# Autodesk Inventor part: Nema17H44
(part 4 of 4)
sketch "Эскиз150"
  geometry: L1 (-96.15, 213.848)-(-96.15, 216.33) reference; L2 (-103.85, 213.848)-(-96.15, 213.848) reference; L3 (-103.85, 216.33)-(-103.85, 213.848) reference; L4 (-92.5, 209.772)-(-107.5, 209.772) reference; L5 (-92.5, 204.772)-(-92.5, 209.772) reference; L6 (-107.5, 204.772)-(-92.5, 204.772) reference; L7 (-107.5, 209.772)-(-107.5, 204.772) reference; L8 (-107.5, 211.772)-(-107.5, 202.772); L9 (-107.5, 202.772)-(-92.5, 202.772); L10 (-92.5, 202.772)-(-92.5, 211.772); L11 (-103.85, 213.848)-(-103.85, 211.748); L12 (-103.85, 211.748)-(-96.15, 211.748); L13 (-96.15, 211.748)-(-96.15, 213.848); L14 (-92.5, 211.772)-(-96.15, 211.772); L15 (-103.85, 211.772)-(-107.5, 211.772); L16 (-100, 225.696)-(-100, 229.696); L17 (-112, 225.696)-(-112, 229.696); L18 (-88, 229.696)-(-88, 225.696); L19 (-96.15, 213.848)-(-98.096, 213.848); L20 (-101.904, 213.848)-(-103.85, 213.848); L21 (-84.45, 245.246)-(-84.45, 241.246); L22 (-85.85, 245.246)-(-85.85, 241.246); L23 (-83.05, 241.246)-(-83.05, 245.246); L24 (-84.45, 243.246)-(-115.55, 243.246); L25 (-115.55, 243.246)-(-115.55, 212.146); L26 (-115.55, 212.146)-(-84.45, 212.146); L27 (-84.45, 212.146)-(-84.45, 243.246); L28 (-84.45, 214.146)-(-84.45, 210.146); L29 (-85.85, 214.146)-(-85.85, 210.146); L30 (-83.05, 210.146)-(-83.05, 214.146); L31 (-115.55, 245.246)-(-115.55, 241.246); L32 (-116.95, 245.246)-(-116.95, 241.246); L33 (-114.15, 241.246)-(-114.15, 245.246); L34 (-115.55, 214.146)-(-115.55, 210.146); L35 (-116.95, 214.146)-(-116.95, 210.146); L36 (-114.15, 210.146)-(-114.15, 214.146); L37 (-124, 246.139)-(-124, -18.443) reference; L38 (-124, 113.848)-(-84.45, 113.848); L39 (-103.85, 13.848)-(-96.15, 13.848); L40 (-96.15, 13.848)-(-98.096, 13.848); L41 (-101.904, 13.848)-(-103.85, 13.848); L42 (-103.85, 15.924)-(-107.5, 15.924); L43 (-103.85, 13.848)-(-103.85, 15.948); L44 (-103.85, 15.948)-(-96.15, 15.948); L45 (-96.15, 15.948)-(-96.15, 13.848); L46 (-92.5, 15.924)-(-96.15, 15.924); L47 (-96.15, 13.848)-(-96.15, 11.366); L48 (-103.85, 11.366)-(-103.85, 13.848); L49 (-100, 2)-(-100, -2); L50 (-115.55, 15.55)-(-84.45, 15.55); L51 (-84.45, 15.55)-(-84.45, -15.55); L52 (-112, 2)-(-112, -2); L53 (-84.45, -15.55)-(-115.55, -15.55); L54 (-88, -2)-(-88, 2); L55 (-92.5, 17.924)-(-107.5, 17.924); L56 (-92.5, 22.924)-(-92.5, 17.924); L57 (-107.5, 22.924)-(-92.5, 22.924); L58 (-107.5, 17.924)-(-107.5, 22.924); L59 (-107.5, 15.924)-(-107.5, 24.924); L60 (-107.5, 24.924)-(-92.5, 24.924); L61 (-92.5, 24.924)-(-92.5, 15.924); L62 (-85.85, 13.55)-(-85.85, 17.55); L63 (-84.45, 13.55)-(-84.45, 17.55); L64 (-83.05, 17.55)-(-83.05, 13.55)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; C1 r 1.4 at (-84.45, 243.246) reference; C2 r 1.4 at (-84.45, 212.146) reference; C3 r 1.4 at (-115.55, 212.146) reference; C4 r 1.4 at (-115.55, 243.246) reference; C5 r 1.4 at (-84.45, 15.55); C6 r 1.4 at (-115.55, 15.55); C7 r 1.4 at (-115.55, -15.55); C8 r 1.4 at (-84.45, -15.55); A1 r 12 centre (-100, 227.696) between (-96.15, 216.33) and (-103.85, 216.33) reference; A2 r 12 centre (-100, 229.696) between (-88, 229.696) and (-112, 229.696); A3 r 12 centre (-100, 225.696) between (-112, 225.696) and (-101.904, 213.848); A4 r 12 centre (-100, 225.696) between (-98.096, 213.848) and (-88, 225.696); A5 r 1.4 centre (-84.45, 245.246) between (-83.05, 245.246) and (-85.85, 245.246); A6 r 1.4 centre (-84.45, 241.246) between (-85.85, 241.246) and (-83.05, 241.246); A7 r 1.4 centre (-84.45, 210.146) between (-85.85, 210.146) and (-83.05, 210.146); A8 r 1.4 centre (-84.45, 214.146) between (-83.05, 214.146) and (-85.85, 214.146); A9 r 1.4 centre (-115.55, 241.246) between (-116.95, 241.246) and (-114.15, 241.246); A10 r 1.4 centre (-115.55, 245.246) between (-114.15, 245.246) and (-116.95, 245.246); A11 r 1.4 centre (-115.55, 210.146) between (-116.95, 210.146) and (-114.15, 210.146); A12 r 1.4 centre (-115.55, 214.146) between (-114.15, 214.146) and (-116.95, 214.146); A13 r 12 centre (-100, 0) between (-103.85, 11.366) and (-96.15, 11.366); A14 r 12 centre (-100, 2) between (-101.904, 13.848) and (-112, 2); A15 r 12 centre (-100, 2) between (-88, 2) and (-98.096, 13.848); A16 r 12 centre (-100, -2) between (-112, -2) and (-88, -2); A17 r 1.4 centre (-84.45, 13.55) between (-85.85, 13.55) and (-83.05, 13.55); A18 r 1.4 centre (-84.45, 17.55) between (-83.05, 17.55) and (-85.85, 17.55); A19 r 1.4 centre (-115.55, 17.55) between (-114.15, 17.55) and (-116.95, 17.55); A20 r 1.4 centre (-115.55, 13.55) between (-116.95, 13.55) and (-114.15, 13.55); A21 r 1.4 centre (-115.55, -13.55) between (-114.15, -13.55) and (-116.95, -13.55); A22 r 1.4 centre (-115.55, -17.55) between (-116.95, -17.55) and (-114.15, -17.55); A23 r 1.4 centre (-84.45, -17.55) between (-85.85, -17.55) and (-83.05, -17.55); A24 r 1.4 centre (-84.45, -13.55) between (-83.05, -13.55) and (-85.85, -13.55); 15 further points
  constraints: 152 end point, 56 symmetric about line, 46 point on circle, 27 centre point, 10 parallel, 10 tangent, 7 horizontal, 5 collinear, 5 perpendicular, 4 point on line, 4 vertical, 3 midpoint, 49 other
  dimensions: "d990" = 2 distance between parallel lines of L6 L9; "d991" = 2.1 distance of L11.end L11.start; "d992" = 2 distance between parallel lines of L4 L14; "d993" = 2 distance of A1.centre L16.end; "d994" = 2 distance of L24.start L21.end; "d995" = 31.1 distance of L26.end L24.start (derived); "d998" = 31.1 distance of L21.end L28.end (derived); "d1001" = 31.1 distance of L21.end L31.end (derived)
extrude "Выдавливание121" cut sketch "Эскиз150" distance "d1004" = 4; taper "d1005" = 0 deg
fillet "Сопряжение51" dims "d1006" = 1
sketch "Эскиз151"
  geometry: C1 r 6.8 at (0, 0) reference; C2 r 6.8 at (0, -227.696) reference; 1 further point
extrude "Выдавливание122" join sketch "Эскиз151" stored distance "d1007" = 98; taper "d1008" = 0 deg
fillet "Сопряжение52" dims "d1009" = 5
fillet "Сопряжение53" dims "d1010" = 5
sketch "Эскиз152"
  geometry: L1 (-124, 16.443)-(-124, 20.443); L2 (-120.75, 16.443)-(-120.75, 20.443); L3 (-127.25, 20.443)-(-127.25, 16.443); L4 (-124, 248.139)-(-124, 244.139); L5 (-127.25, 248.139)-(-127.25, 244.139); L6 (-120.75, 244.139)-(-120.75, 248.139); C1 r 4.05 at (-124, 18.443) reference; C2 r 4.05 at (-124, 246.139) reference; C3 r 3.25 at (-124, 18.443); A1 r 3.25 centre (-124, 16.443) between (-127.25, 16.443) and (-120.75, 16.443); A2 r 3.25 centre (-124, 20.443) between (-120.75, 20.443) and (-127.25, 20.443); A3 r 3.25 centre (-124, 248.139) between (-120.75, 248.139) and (-127.25, 248.139); A4 r 3.25 centre (-124, 244.139) between (-127.25, 244.139) and (-120.75, 244.139); 1 further point
  constraints: 16 end point, 9 tangent, 8 point on circle, 5 centre point, 2 midpoint, 2 parallel, 2 vertical, 1 coincident, 1 collinear, 1 equal radius
  dimensions: "d1011" = 2 distance of C1.centre L1.end; "d1012" = 6.5 diameter of C3
extrude "Выдавливание123" cut sketch "Эскиз152" distance "d1013" = 10; taper "d1014" = 0 deg
node "РабПлоскость14"
sketch "Эскиз153" dims "d1020" = 12
  geometry: L1 (-18.21, -243.972)-(-18.21, -263.972); L2 (-18.21, -243.972)-(-20.91, -243.972); L3 (-20.91, -243.972)-(-19.63, -245.252); L4 (-19.63, -245.252)-(-19.63, -263.472); L5 (-19.63, -263.472)-(-19.13, -263.972); L6 (-19.13, -263.972)-(-18.21, -263.972); L7 (-35.46, -275.972)-(-0.96, -275.972) reference; 3 further points
  constraints: 12 end point, 3 horizontal, 2 parallel, 1 perpendicular, 1 point on line, 1 vertical, 1 vertical alignment, 2 other
  dimensions: "d1015" = 5.4 diameter of L2.end L1; "d1016" = 2.84 diameter of L4 L1; "d1017" = 20 distance of L1.end L1.start; "d1018" = 45 deg angle of L6 L5; "d1019" = 0.5 horizontal distance of L4.end L5.end
revolve "Вращение3" sketch "Эскиз153" stored, may be unused: angle "d1021" = 90 deg
sketch "Эскиз154"
  geometry: L1 (-25.71, -238.252)-(-10.71, -238.252); L2 (-10.71, -238.252)-(-10.71, -245.252); L3 (-10.71, -245.252)-(-25.71, -245.252); L4 (-25.71, -245.252)-(-25.71, -238.252); L5 (-20.91, -245.252)-(-15.51, -245.252); L6 (-15.51, -245.252)-(-15.51, -243.372); L7 (-15.51, -243.372)-(-20.91, -243.372); L8 (-20.91, -243.372)-(-20.91, -245.252); L9 (-19.63, -245.252)-(-16.79, -245.252) reference; L10 (-20.91, -243.972)-(-15.51, -243.972) reference; L11 (-20.91, -243.972)-(-19.63, -245.252) reference; L12 (-25.71, -245.252)-(-20.91, -245.252); L13 (-18.21, -238.252)-(-18.21, -245.252); 3 further points
  constraints: 20 end point, 4 parallel, 3 horizontal, 3 midpoint, 3 point on line, 2 perpendicular, 1 collinear, 1 vertical alignment
  dimensions: "d1022" = 7 distance of L1.end L2.end; "d1023" = 15 distance of L1.start L1.end; "d1024" = 0.6 distance between parallel lines of L10 L7
revolve "Вращение4" sketch "Эскиз154" stored, may be unused: angle "d1025" = 90 deg
chamfer "Фаска48" distance "d1026" = 1; stored, may be unused: second distance "d1027" = 2, angle "d1028" = 45 deg
sketch "Эскиз155"
  geometry: C1 r 6.5 at (0, 0) reference; A1 r 7.5 centre (0, 0) between (7.499, -0.146) and (6.791, -3.184) reference; A2 r 1 centre (7.499, -0.146) between (7.038, 0.741) and (7.004, -1.015); A3 r 0.627 centre (6.694, -1.56) between (6.731, -2.185) and (7.004, -1.015); A4 r 1 centre (6.791, -3.184) between (6.731, -2.185) and (5.985, -3.776); A5 r 7.077 centre (0, 0) between (7.004, -1.015) and (5.985, -3.776); A6 r 1 centre (7.499, -0.146) between (7.038, 0.741) and (7.004, -1.015); A7 r 0.627 centre (6.75, 1.298) between (7.038, 0.741) and (6.811, 1.921); A8 r 1 centre (6.91, 2.916) between (6.128, 3.54) and (6.811, 1.921); A9 r 1 centre (6.91, 2.916) between (6.128, 3.54) and (6.811, 1.921); A10 r 0.627 centre (5.639, 3.931) between (6.128, 3.54) and (5.441, 4.525); A11 r 1 centre (5.126, 5.475) between (4.159, 5.727) and (5.441, 4.525); A12 r 1 centre (5.126, 5.475) between (4.159, 5.727) and (5.441, 4.525); A13 r 0.627 centre (3.552, 5.884) between (4.159, 5.727) and (3.13, 6.347); A14 r 1 centre (2.456, 7.086) between (1.47, 6.923) and (3.13, 6.347); A15 r 1 centre (2.456, 7.086) between (1.47, 6.923) and (3.13, 6.347); A16 r 0.627 centre (0.852, 6.821) between (1.47, 6.923) and (0.278, 7.072); A17 r 1 centre (-0.638, 7.473) between (-1.473, 6.922) and (0.278, 7.072); A18 r 1 centre (-0.638, 7.473) between (-1.473, 6.922) and (0.278, 7.072); A19 r 0.627 centre (-1.996, 6.577) between (-1.473, 6.922) and (-2.623, 6.573); A20 r 1 centre (-3.623, 6.567) between (-4.161, 5.725) and (-2.623, 6.573); A21 r 1 centre (-3.623, 6.567) between (-4.161, 5.725) and (-2.623, 6.573); A22 r 0.627 centre (-4.499, 5.197) between (-4.161, 5.725) and (-5.069, 4.938); A23 r 1 centre (-5.98, 4.526) between (-6.13, 3.537) and (-5.069, 4.938); A24 r 1 centre (-5.98, 4.526) between (-6.13, 3.537) and (-5.069, 4.938); A25 r 0.627 centre (-6.223, 2.918) between (-6.13, 3.537) and (-6.64, 2.45); A26 r 1 centre (-7.304, 1.702) between (-7.039, 0.738) and (-6.64, 2.45); A27 r 1 centre (-7.304, 1.702) between (-7.039, 0.738) and (-6.64, 2.45); A28 r 0.627 centre (-6.872, 0.134) between (-7.039, 0.738) and (-7.062, -0.463); A29 r 1 centre (-7.365, -1.416) between (-6.73, -2.189) and (-7.062, -0.463); A30 r 1 centre (-7.365, -1.416) between (-6.73, -2.189) and (-7.062, -0.463); A31 r 0.627 centre (-6.333, -2.673) between (-6.73, -2.189) and (-6.263, -3.295); A32 r 1 centre (-6.153, -4.289) between (-5.258, -4.737) and (-6.263, -3.295); A33 r 1 centre (-6.153, -4.289) between (-5.258, -4.737) and (-6.263, -3.295); A34 r 0.627 centre (-4.698, -5.017) between (-5.258, -4.737) and (-4.381, -5.558); A35 r 1 centre (-3.876, -6.421) between (-2.877, -6.466) and (-4.381, -5.558); A36 r 1 centre (-3.876, -6.421) between (-2.877, -6.466) and (-4.381, -5.558); A37 r 0.627 centre (-2.251, -6.494) between (-2.877, -6.466) and (-1.742, -6.859); A38 r 1 centre (-0.929, -7.442) between (0.002, -7.077) and (-1.742, -6.859); A39 r 1 centre (-0.929, -7.442) between (0.002, -7.077) and (-1.742, -6.859); A40 r 0.627 centre (0.585, -6.849) between (0.002, -7.077) and (1.199, -6.975); A41 r 1 centre (2.178, -7.177) between (2.88, -6.465) and (1.199, -6.975); A42 r 1 centre (2.178, -7.177) between (2.88, -6.465) and (1.199, -6.975); A43 r 0.627 centre (3.32, -6.019) between (2.88, -6.465) and (3.932, -5.884); A44 r 1 centre (4.909, -5.67) between (5.26, -4.734) and (3.932, -5.884); A45 r 1 centre (4.909, -5.67) between (5.26, -4.734) and (3.932, -5.884); A46 r 0.627 centre (5.481, -4.148) between (5.26, -4.734) and (5.985, -3.776); A47 r 1 centre (6.791, -3.184) between (6.731, -2.185) and (5.985, -3.776); 31 further points
  constraints: 95 point on circle, 46 centre point, 4 tangent, 1 coincident, 1 concentric, 1 equal radius, 151 other
  dimensions: "d1035" = 360 deg dimension on A1.centre A1.end (derived)
extrude "Выдавливание124" cut sketch "Эскиз155" distance "d1037" = 40; taper "d1038" = 0 deg
fillet "Сопряжение54" dims "d1039" = 1
fillet "Сопряжение55" dims "d1040" = 1
sketch "Эскиз156"
  geometry: L1 (-9.071, 18.521)-(-2, 11.45) reference; L2 (-2, 11.45)-(-9.071, 4.379) reference; L3 (-14, 10.53)-(-14, 12.37) reference; L4 (-9.029, 6.479)-(-9.029, 16.421); A1 r 4.971 centre (-9.029, 11.45) between (-9.029, 6.479) and (-9.029, 16.421); 1 further point
  constraints: 3 tangent, 2 end point, 2 point on circle, 1 centre point, 1 midpoint, 1 vertical
  dimensions: "d1041" = 9.94113 diameter of A1 (derived)
feature "ВыдавПврх2" sketch "Эскиз156" dims "d1042" = 40, "d1043" = 0
sketch "Эскиз157"
  geometry: L1 (-1.5, -4.029)-(-1.5, 13.971) reference; L2 (-1.5, 4.971)-(-1.5, 9.941); L3 (-1.5, 9.941)-(-70.5, 9.941); L4 (-70.5, 9.941)-(-74.5, 7.771); L5 (-74.5, 7.771)-(-94.5, 7.771); L6 (0, -6.079)-(0, 16.021) reference; L7 (0, 4.971)-(-99.5, 4.971); L8 (-123.5, 101.759)-(-123.5, -98.241) reference; L9 (-94.5, 7.771)-(-94.5, 5.971); L10 (-94.5, 5.971)-(-94.5, 7.771); L11 (-1.5, 9.941)-(20.5, 9.941); L12 (20.5, 9.941)-(20.5, 4.971); L13 (20.5, 4.971)-(0, 4.971); A1 r 37.185 centre (-94.5, -31.214) between (-94.5, 5.971) and (-98.637, 5.74); A2 r 1 centre (-98.526, 4.746) between (-98.637, 5.74) and (-99.5, 4.971); 3 further points
  constraints: 20 end point, 4 point on circle, 3 vertical, 2 centre point, 2 horizontal, 2 midpoint, 2 parallel, 1 line through centre, 1 perpendicular, 1 point on line, 1 tangent
  dimensions: "d1044" = 24 distance from line of L8 L7.end; "d1045" = 9.941 diameter of L3 L7; "d1046" = 5.6 diameter of L5 L7; "d1047" = 5 horizontal distance of L9.end L7.end; "d1048" = 24 horizontal distance of L5.end L3.end; "d1049" = 4 horizontal distance of L3.end L4.end; "d1050" = 2 diameter of L9.end L7; "d1051" = 1 radius of A2; "d1053" = 120 horizontal distance of L7.end L11.end
revolve "Вращение5" sketch "Эскиз157" stored, may be unused: angle "d1052" = 359.817 deg
sketch "Эскиз158"
  geometry: L1 (0, 0)-(0, 99) reference; L2 (44, 0)-(0, 0) reference; L3 (44, 99)-(44, 0) reference; L4 (0, 99)-(44, 99) reference; L5 (22, 14.5)-(22, 84.5); C1 r 1.65 at (22, 14.5); C2 r 1.65 at (22, 84.5); 4 further points
  constraints: 3 midpoint, 2 centre point, 2 end point, 1 equal radius, 1 horizontal alignment, 1 vertical, 1 vertical alignment
  dimensions: "d1057" = 3.3 diameter of C2; "d1058" = 70 distance of L5.start L5.end
  node "Спроецированная петля78"
sketch "Эскиз159"
  geometry: 1 further point
sketch "Эскиз160"
  geometry: L1 (-50.4, 0.857)-(-46.4, 0.857); L2 (-46.4, 0.857)-(-46.4, 263.076); L3 (-46.4, 263.076)-(-50.4, 263.076); L4 (-50.4, 263.076)-(-50.4, 0.857); L5 (-46, 34.614)-(-46, 2.271) reference; A1 r 2 centre (-44, 262.31) between (-45.414, 263.724) and (-46, 262.31) reference; 3 further points
  constraints: 8 end point, 2 parallel, 2 point on line, 1 horizontal, 1 perpendicular, 1 point on circle
  dimensions: "d1059" = 4 distance of L2.end L3.end; "d1061" = 0.4 distance between parallel lines of L5 L2
extrude "Выдавливание125" new body sketch "Эскиз160" distance "d1062" = 12; taper "d1063" = 0 deg
sketch "Эскиз161"
  geometry: L1 (50.4, 263.076)-(46.4, 263.076); L2 (46.4, 263.076)-(46.4, 228.076); L3 (46.4, 228.076)-(50.4, 228.076); L4 (50.4, 228.076)-(50.4, 263.076); L5 (50.4, 263.076)-(50.4, 0.857) reference; L6 (46.4, 0.857)-(46.4, 263.076) reference; L7 (46.4, 263.076)-(50.4, 263.076) reference; L8 (50.4, 187.336)-(46.4, 187.336); L9 (46.4, 187.336)-(46.4, 152.336); L10 (46.4, 152.336)-(50.4, 152.336); L11 (50.4, 152.336)-(50.4, 187.336); L12 (50.4, 111.596)-(46.4, 111.596); L13 (46.4, 111.596)-(46.4, 76.596); L14 (46.4, 76.596)-(50.4, 76.596); L15 (50.4, 76.596)-(50.4, 111.596); L16 (50.4, 35.857)-(46.4, 35.857); L17 (46.4, 35.857)-(46.4, 0.857); L18 (46.4, 0.857)-(50.4, 0.857); L19 (50.4, 0.857)-(50.4, 35.857); L20 (50.4, 0.857)-(46.4, 0.857) reference; 14 further points
  constraints: 32 end point, 3 collinear, 2 parallel, 1 horizontal, 1 midpoint, 1 perpendicular, 1 vertical, 24 other
  dimensions: "d1064" = 0 distance from line of point (48.4, 263.076) L1; "d1067" = 75.73958 distance of L1.start L8.start (derived); "d1072" = 35 distance between parallel lines of L3 L1
extrude "Выдавливание126" join sketch "Эскиз161" distance "d1073" = 4; taper "d1074" = 0 deg
feature "Комбинировать10"
feature "Толщина10" dims "d1075" = 0.1, "d1076" = 0.1
feature "Толщина11" dims "d1077" = 0.1, "d1078" = 0.1
feature "Толщина12" dims "d1079" = 0.1, "d1080" = 0.1
feature "Толщина13" dims "d1081" = 0.1, "d1082" = 0.1
sketch "Эскиз162"
  geometry: L1 (-5.7, 191.022)-(-30.7, 191.022); L2 (-30.7, 191.022)-(-30.7, 176.022); L3 (-30.7, 176.022)-(-5.7, 176.022); L4 (-5.7, 176.022)-(-5.7, 191.022); L5 (-124, -18.443)-(-124, 246.139) reference; L6 (-124, 113.848)-(-29.515, 113.848); L7 (-5.7, 36.674)-(-30.7, 36.674); L8 (-30.7, 36.674)-(-30.7, 51.674); L9 (-30.7, 51.674)-(-5.7, 51.674); L10 (-5.7, 51.674)-(-5.7, 36.674); L11 (13.8, 61.348)-(-50.2, 61.348) reference; L12 (-50.2, 166.348)-(13.8, 166.348) reference; L13 (1.5, 200.696)-(13, 200.696) reference; L14 (-18.2, 195.622)-(-18.2, 171.422); C1 r 1.6 at (-18.2, 195.622); C2 r 1.6 at (-18.2, 171.422); C3 r 1.6 at (-18.2, 32.074); C4 r 1.6 at (-18.2, 56.274); 6 further points
  constraints: 20 end point, 6 midpoint, 6 symmetric about line, 4 centre point, 2 horizontal, 2 parallel, 2 point on line, 1 horizontal alignment, 1 perpendicular, 1 vertical, 1 vertical alignment, 2 other
  dimensions: "d1083" = 15 distance of L3.end L1.start; "d1084" = 25 distance of L1.start L1.end; "d1085" = 9.674 distance between parallel lines of L1 L13 (derived); "d1086" = 9.674 distance between parallel lines of L12 L3 (derived); "d1087" = 3.2 diameter of C2; "d1088" = 3.2 diameter of C1; "d1089" = 3 distance edge to line of C1 L1
extrude "Выдавливание127" cut sketch "Эскиз162" distance "d1090" = 4; taper "d1091" = 0 deg
fillet "Сопряжение56" dims "d1092" = 3
sketch "Эскиз164"
  geometry: L1 (3, 92.288)-(3, 191.288) reference; L2 (47, 92.288)-(3, 92.288) reference; L3 (47, 191.288)-(47, 92.288) reference; L4 (3, 191.288)-(47, 191.288) reference; C1 r 1.65 at (25, 176.788) reference; C2 r 1.65 at (25, 106.788) reference; 1 further point
extrude "Выдавливание128" cut sketch "Эскиз164" stored distance "d1094" = 10; taper "d1095" = 0 deg
sketch "Эскиз165"
  geometry: L1 (50.2, 163.348)-(50.2, 64.348) reference; L2 (-13.8, 163.348)-(50.2, 163.348) reference; L3 (-13.8, 64.348)-(-13.8, 163.348) reference; L4 (50.2, 64.348)-(-13.8, 64.348) reference; C1 r 1.6 at (18.2, 148.848) reference; C2 r 1.6 at (18.2, 78.848) reference; 1 further point
extrude "Выдавливание129" cut sketch "Эскиз165" distance "d1096" = 100; taper "d1097" = 0 deg
sketch "Эскиз166"
  geometry: L1 (-96.3, 194.465)-(-115.3, 194.465) reference; L2 (-118.3, 197.465)-(-118.3, 206.465) reference; L3 (-115.3, 209.465)-(-96.3, 209.465) reference; L4 (-93.3, 206.465)-(-93.3, 197.465) reference; L5 (-93.3, 67.117)-(-93.3, 58.117) reference; L6 (-96.3, 55.117)-(-115.3, 55.117) reference; L7 (-118.3, 58.117)-(-118.3, 67.117) reference; L8 (-115.3, 70.117)-(-96.3, 70.117) reference; L9 (-46.3, 35.957)-(-46.3, 0.757) reference; L10 (-46.3, 0.757)-(-50.5, 0.757) reference; L11 (-50.5, 0.757)-(-50.5, 35.957) reference; L12 (-50.5, 35.957)-(-46.3, 35.957) reference; L13 (-46.3, 111.696)-(-46.3, 76.496) reference; L14 (-46.3, 76.496)-(-50.5, 76.496) reference; L15 (-50.5, 76.496)-(-50.5, 111.696) reference; L16 (-50.5, 111.696)-(-46.3, 111.696) reference; L17 (-46.3, 187.436)-(-46.3, 152.236) reference; L18 (-46.3, 152.236)-(-50.5, 152.236) reference; L19 (-50.5, 152.236)-(-50.5, 187.436) reference; L20 (-50.5, 187.436)-(-46.3, 187.436) reference; L21 (-50.5, 263.176)-(-46.3, 263.176) reference; L22 (-46.3, 263.176)-(-46.3, 227.976) reference; L23 (-46.3, 227.976)-(-50.5, 227.976) reference; L24 (-50.5, 227.976)-(-50.5, 263.176) reference; L25 (-127.25, 16.443)-(-127.25, 20.443) reference; L26 (-120.75, 20.443)-(-120.75, 16.443) reference; L27 (-120.75, 248.139)-(-120.75, 244.139) reference; L28 (-127.25, 244.139)-(-127.25, 248.139) reference; L29 (-20.15, 33.367)-(-20.15, 32.504) reference; L30 (-27.85, 32.504)-(-27.85, 33.367) reference; L31 (-28.85, 34.367)-(-30.5, 34.367) reference; L32 (-31.5, 35.367)-(-31.5, 42.367) reference; L33 (-30.5, 43.367)-(-17.5, 43.367) reference; L34 (-16.5, 42.367)-(-16.5, 35.367) reference; L35 (-17.5, 34.367)-(-19.15, 34.367) reference; L36 (-19.15, 230.215)-(-17.5, 230.215) reference; L37 (-16.5, 229.215)-(-16.5, 222.215) reference; L38 (-17.5, 221.215)-(-30.5, 221.215) reference; L39 (-31.5, 222.215)-(-31.5, 229.215) reference; L40 (-30.5, 230.215)-(-28.85, 230.215) reference; L41 (-27.85, 231.215)-(-27.85, 232.077) reference; L42 (-20.15, 232.077)-(-20.15, 231.215) reference; L43 (-120.15, 230.315)-(-119.5, 230.315) reference; L44 (-118.5, 229.315)-(-118.5, 222.115) reference; L45 (-119.5, 221.115)-(-128.5, 221.115) reference; L46 (-129.5, 222.115)-(-129.5, 229.315) reference; L47 (-128.5, 230.315)-(-127.85, 230.315) reference; L48 (-126.85, 231.315)-(-126.85, 236.391) reference; L49 (-125.85, 237.391)-(-122.15, 237.391) reference; L50 (-121.15, 236.391)-(-121.15, 231.315) reference; L51 (-145, 249.179)-(-140.9, 249.179) reference; L52 (-140.9, 249.179)-(-140.9, 218.979) reference; L53 (-140.9, 218.979)-(-145, 218.979) reference; L54 (-145, 218.979)-(-145, 181.32) reference; L55 (-145, 181.32)-(-140.9, 181.32) reference; L56 (-140.9, 181.32)-(-140.9, 151.12) reference; L57 (-140.9, 151.12)-(-145, 151.12) reference; L58 (-145, 151.12)-(-145, 113.461) reference; L59 (-145, 113.461)-(-140.9, 113.461) reference; L60 (-140.9, 113.461)-(-140.9, 83.261) reference; L61 (-140.9, 83.261)-(-145, 83.261) reference; L62 (-145, 83.261)-(-145, 45.602) reference; L63 (-145, 45.602)-(-140.9, 45.602) reference; L64 (-140.9, 45.602)-(-140.9, 15.402) reference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; C1 r 1.6 at (-105.8, 167.291) reference; C2 r 1.6 at (-105.8, 97.291) reference; C3 r 1.6 at (-105.8, 50.517) reference; C4 r 1.6 at (-105.8, 189.865) reference; C5 r 1.6 at (-105.8, 74.717) reference; C6 r 1.6 at (-105.8, 214.065) reference; A1 r 3 centre (-115.3, 197.465) between (-118.3, 197.465) and (-115.3, 194.465) reference; A2 r 3 centre (-115.3, 206.465) between (-115.3, 209.465) and (-118.3, 206.465) reference; A3 r 3 centre (-96.3, 206.465) between (-93.3, 206.465) and (-96.3, 209.465) reference; A4 r 3 centre (-96.3, 197.465) between (-96.3, 194.465) and (-93.3, 197.465) reference; A5 r 3 centre (-96.3, 58.117) between (-96.3, 55.117) and (-93.3, 58.117) reference; A6 r 3 centre (-115.3, 58.117) between (-118.3, 58.117) and (-115.3, 55.117) reference; A7 r 3 centre (-115.3, 67.117) between (-115.3, 70.117) and (-118.3, 67.117) reference; A8 r 3 centre (-96.3, 67.117) between (-93.3, 67.117) and (-96.3, 70.117) reference; A9 r 3.25 centre (-124, 20.443) between (-120.75, 20.443) and (-127.25, 20.443) reference; A10 r 3.25 centre (-124, 16.443) between (-127.25, 16.443) and (-120.75, 16.443) reference; A11 r 3.25 centre (-124, 244.139) between (-127.25, 244.139) and (-120.75, 244.139) reference; A12 r 3.25 centre (-124, 248.139) between (-120.75, 248.139) and (-127.25, 248.139) reference; A13 r 1 centre (-19.15, 33.367) between (-19.15, 34.367) and (-20.15, 33.367) reference; A14 r 1 centre (-19.15, 32.504) between (-20.15, 32.504) and (-19.523, 31.576) reference; A15 r 12 centre (-24, 20.443) between (-13.209, 25.693) and (-19.523, 31.576) reference; A16 r 13 centre (-24, 18.443) between (-13.209, 11.193) and (-13.209, 25.693) reference; A17 r 12 centre (-24, 16.443) between (-34.791, 11.193) and (-13.209, 11.193) reference; A18 r 13 centre (-24, 18.443) between (-34.791, 25.693) and (-34.791, 11.193) reference; A19 r 12 centre (-24, 20.443) between (-28.477, 31.576) and (-34.791, 25.693) reference; A20 r 1 centre (-28.85, 32.504) between (-28.477, 31.576) and (-27.85, 32.504) reference; A21 r 1 centre (-28.85, 33.367) between (-27.85, 33.367) and (-28.85, 34.367) reference; A22 r 1 centre (-30.5, 35.367) between (-31.5, 35.367) and (-30.5, 34.367) reference; A23 r 1 centre (-30.5, 42.367) between (-30.5, 43.367) and (-31.5, 42.367) reference; A24 r 1 centre (-17.5, 42.367) between (-16.5, 42.367) and (-17.5, 43.367) reference; A25 r 1 centre (-17.5, 35.367) between (-17.5, 34.367) and (-16.5, 35.367) reference; A26 r 1 centre (-19.15, 231.215) between (-20.15, 231.215) and (-19.15, 230.215) reference; A27 r 1 centre (-17.5, 229.215) between (-16.5, 229.215) and (-17.5, 230.215) reference; A28 r 1 centre (-17.5, 222.215) between (-17.5, 221.215) and (-16.5, 222.215) reference; A29 r 1 centre (-30.5, 222.215) between (-31.5, 222.215) and (-30.5, 221.215) reference; A30 r 1 centre (-30.5, 229.215) between (-30.5, 230.215) and (-31.5, 229.215) reference; A31 r 1 centre (-28.85, 231.215) between (-28.85, 230.215) and (-27.85, 231.215) reference; A32 r 1 centre (-28.85, 232.077) between (-27.85, 232.077) and (-28.477, 233.005) reference; A33 r 12 centre (-24, 244.139) between (-34.791, 238.889) and (-28.477, 233.005) reference; A34 r 13 centre (-24, 246.139) between (-34.791, 253.389) and (-34.791, 238.889) reference; A35 r 12 centre (-24, 248.139) between (-13.209, 253.389) and (-34.791, 253.389) reference; A36 r 13 centre (-24, 246.139) between (-13.209, 238.889) and (-13.209, 253.389) reference; A37 r 12 centre (-24, 244.139) between (-19.523, 233.005) and (-13.209, 238.889) reference; A38 r 1 centre (-19.15, 232.077) between (-19.523, 233.005) and (-20.15, 232.077) reference; A39 r 1 centre (-120.15, 231.315) between (-121.15, 231.315) and (-120.15, 230.315) reference; A40 r 1 centre (-119.5, 229.315) between (-118.5, 229.315) and (-119.5, 230.315) reference; A41 r 1 centre (-119.5, 222.115) between (-119.5, 221.115) and (-118.5, 222.115) reference; A42 r 1 centre (-128.5, 222.115) between (-129.5, 222.115) and (-128.5, 221.115) reference; A43 r 1 centre (-128.5, 229.315) between (-128.5, 230.315) and (-129.5, 229.315) reference; A44 r 1 centre (-127.85, 231.315) between (-127.85, 230.315) and (-126.85, 231.315) reference; A45 r 1 centre (-125.85, 236.391) between (-125.85, 237.391) and (-126.85, 236.391) reference; A46 r 1 centre (-122.15, 236.391) between (-121.15, 236.391) and (-122.15, 237.391) reference; A47 r 6 centre (-139, -9.498) between (-145, -9.498) and (-138.592, -15.484) reference; A48 r 6 centre (-139, 274.079) between (-138.592, 280.065) and (-145, 274.079) reference; A49 r 1.65 centre (-134.4, 260.579) between (-132.75, 260.579) and (-136.05, 260.579) reference; A50 r 1.65 centre (-134.4, 252.579) between (-136.05, 252.579) and (-132.75, 252.579) reference; A51 r 1.65 centre (-124, 263.639) between (-122.35, 263.639) and (-125.65, 263.639) reference; A52 r 1.65 centre (-124, 258.639) between (-125.65, 258.639) and (-122.35, 258.639) reference; A53 r 1.65 centre (-136.99, 241.139) between (-135.34, 241.139) and (-138.64, 241.139) reference; A54 r 1.65 centre (-136.99, 236.139) between (-138.64, 236.139) and (-135.34, 236.139) reference; A55 r 1.65 centre (-111.01, 241.139) between (-109.36, 241.139) and (-112.66, 241.139) reference; A56 r 1.65 centre (-111.01, 236.139) between (-112.66, 236.139) and (-109.36, 236.139) reference; A57 r 1 centre (-120.15, 33.267) between (-120.15, 34.267) and (-121.15, 33.267) reference; A58 r 1 centre (-122.15, 28.191) between (-122.15, 27.191) and (-121.15, 28.191) reference; A59 r 1 centre (-125.85, 28.191) between (-126.85, 28.191) and (-125.85, 27.191) reference; A60 r 1 centre (-127.85, 33.267) between (-126.85, 33.267) and (-127.85, 34.267) reference; A61 r 1 centre (-128.5, 35.267) between (-129.5, 35.267) and (-128.5, 34.267) reference; A62 r 1 centre (-128.5, 42.467) between (-128.5, 43.467) and (-129.5, 42.467) reference; A63 r 1 centre (-119.5, 42.467) between (-118.5, 42.467) and (-119.5, 43.467) reference; A64 r 1 centre (-119.5, 35.267) between (-119.5, 34.267) and (-118.5, 35.267) reference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; 2 further points
  constraints: 36 end point, 19 point on circle, 8 centre point, 8 tangent, 6 parallel, 4 collinear, 4 horizontal, 3 equal radius, 2 equal length, 2 perpendicular, 1 midpoint, 1 point on line, 1 vertical alignment, 7 other
  dimensions: "d1098" = 1.5 distance between parallel lines of L6 L111; "d1099" = 1.8 distance edge to line of C3 L117; "d1101" = 2 distance edge to line of C3 L118; "d1102" = 2 radius of A91 (derived)
extrude "Выдавливание130" new body sketch "Эскиз166" distance "d1103" = 20; taper "d1104" = 0 deg
fillet "Сопряжение57" dims "d1105" = 0.4
sketch "Эскиз167"
  geometry: L1 (-96.3, 71.617)-(-102.2, 71.617) reference; L2 (-102.2, 71.617)-(-102.2, 76.117) reference; L3 (-104.2, 78.117)-(-107.4, 78.117) reference; L4 (-109.4, 76.117)-(-109.4, 71.617) reference; L5 (-109.4, 71.617)-(-115.3, 71.617) reference; L6 (-119.8, 67.117)-(-119.8, 58.117) reference; L7 (-115.3, 53.617)-(-109.4, 53.617) reference; L8 (-109.4, 53.617)-(-109.4, 49.117) reference; L9 (-107.4, 47.117)-(-104.2, 47.117) reference; L10 (-102.2, 49.117)-(-102.2, 53.617) reference; L11 (-102.2, 53.617)-(-96.3, 53.617) reference; L12 (-94.009, 55.117)-(-115.3, 55.117) reference; L13 (-118.3, 58.117)-(-118.3, 67.117) reference; L14 (-115.3, 70.117)-(-94.009, 70.117) reference; L15 (-109.4, 53.617)-(-102.2, 53.617); L16 (-109.4, 71.617)-(-102.2, 71.617); C1 r 1.6 at (-105.8, 74.717) reference; C2 r 1.6 at (-105.8, 50.517) reference; A1 r 0.4 centre (-94.009, 70.517) between (-94.009, 70.117) and (-93.785, 70.848) reference; A2 r 4.5 centre (-96.3, 67.117) between (-93.785, 70.848) and (-96.3, 71.617) reference; A3 r 2 centre (-104.2, 76.117) between (-102.2, 76.117) and (-104.2, 78.117) reference; A4 r 2 centre (-107.4, 76.117) between (-107.4, 78.117) and (-109.4, 76.117) reference; A5 r 4.5 centre (-115.3, 67.117) between (-115.3, 71.617) and (-119.8, 67.117) reference; A6 r 4.5 centre (-115.3, 58.117) between (-119.8, 58.117) and (-115.3, 53.617) reference; A7 r 2 centre (-107.4, 49.117) between (-109.4, 49.117) and (-107.4, 47.117) reference; A8 r 2 centre (-104.2, 49.117) between (-104.2, 47.117) and (-102.2, 49.117) reference; A9 r 4.5 centre (-96.3, 58.117) between (-96.3, 53.617) and (-93.785, 54.385) reference; A10 r 0.4 centre (-94.009, 54.717) between (-93.785, 54.385) and (-94.009, 55.117) reference; A11 r 3 centre (-115.3, 58.117) between (-118.3, 58.117) and (-115.3, 55.117) reference; A12 r 3 centre (-115.3, 67.117) between (-115.3, 70.117) and (-118.3, 67.117) reference; 1 further point
  constraints: 4 end point, 1 horizontal, 1 parallel
extrude "Выдавливание131" cut sketch "Эскиз167" distance "d1106" = 16; taper "d1107" = 0 deg
sketch "Эскиз168"
  geometry: L1 (-104.2, 47.117)-(-107.4, 47.117) reference; L2 (-102.2, 53.617)-(-102.2, 49.117) reference; L3 (-109.4, 53.617)-(-102.2, 53.617) reference; L4 (-109.4, 49.117)-(-109.4, 53.617) reference; L5 (-107.4, 78.117)-(-104.2, 78.117) reference; L6 (-109.4, 71.617)-(-109.4, 76.117) reference; L7 (-102.2, 71.617)-(-109.4, 71.617) reference; L8 (-102.2, 76.117)-(-102.2, 71.617) reference; L9 (-109.033, 50.517)-(-107.417, 53.317); L10 (-107.417, 53.317)-(-104.183, 53.317); L11 (-104.183, 53.317)-(-102.567, 50.517); L12 (-102.567, 50.517)-(-104.183, 47.717); L13 (-104.183, 47.717)-(-107.417, 47.717); L14 (-107.417, 47.717)-(-109.033, 50.517); L15 (-107.417, 71.917)-(-109.033, 74.717); L16 (-109.033, 74.717)-(-107.417, 77.517); L17 (-107.417, 77.517)-(-104.183, 77.517); L18 (-104.183, 77.517)-(-102.567, 74.717); L19 (-102.567, 74.717)-(-104.183, 71.917); L20 (-104.183, 71.917)-(-107.417, 71.917); C1 r 1.6 at (-105.8, 50.517) reference; C2 r 1.6 at (-105.8, 74.717) reference; A1 r 2 centre (-107.4, 49.117) between (-109.4, 49.117) and (-107.4, 47.117) reference; A2 r 2 centre (-104.2, 49.117) between (-104.2, 47.117) and (-102.2, 49.117) reference; A3 r 2 centre (-104.2, 76.117) between (-102.2, 76.117) and (-104.2, 78.117) reference; A4 r 2 centre (-107.4, 76.117) between (-107.4, 78.117) and (-109.4, 76.117) reference; 3 further points
  constraints: 24 end point, 2 coincident, 2 horizontal, 1 parallel, 26 other
  dimensions: "d1108" = 5.6 distance between parallel lines of L13 L10
extrude "Выдавливание132" cut sketch "Эскиз168" distance "d1109" = 1; taper "d1110" = 0 deg
sketch "Эскиз169"
  geometry: L1 (-96.3, 71.617)-(-115.3, 71.617) reference; L2 (-119.8, 67.117)-(-119.8, 58.117) reference; L3 (-115.3, 53.617)-(-96.3, 53.617) reference; L4 (-94.009, 55.117)-(-115.3, 55.117) reference; L5 (-118.3, 58.117)-(-118.3, 67.117) reference; L6 (-115.3, 70.117)-(-94.009, 70.117) reference; L7 (-93.609, 54.015)-(-93.609, 75.806); C1 r 1.6 at (-105.8, 62.617); A1 r 4.5 centre (-115.3, 67.117) between (-115.3, 71.617) and (-119.8, 67.117) reference; A2 r 4.5 centre (-115.3, 58.117) between (-119.8, 58.117) and (-115.3, 53.617) reference; A3 r 4.5 centre (-96.3, 58.117) between (-96.3, 53.617) and (-93.785, 54.385) reference; A4 r 0.4 centre (-94.009, 54.717) between (-93.785, 54.385) and (-94.009, 55.117) reference; A5 r 3 centre (-115.3, 58.117) between (-118.3, 58.117) and (-115.3, 55.117) reference; A6 r 3 centre (-115.3, 67.117) between (-115.3, 70.117) and (-118.3, 67.117) reference; A7 r 0.4 centre (-94.009, 70.517) between (-94.009, 70.117) and (-93.785, 70.848) reference; A8 r 4.5 centre (-96.3, 67.117) between (-93.785, 70.848) and (-96.3, 71.617) reference; A9 r 0.4 centre (-94.009, 70.517) between (-94.009, 70.117) and (-93.785, 70.848) reference; A10 r 0.4 centre (-94.009, 54.717) between (-93.785, 54.385) and (-94.009, 55.117) reference; 5 further points
  constraints: 2 end point, 2 midpoint, 2 tangent, 1 centre point, 1 horizontal alignment, 1 vertical alignment
  dimensions: "d1111" = 3.2 diameter of C1
extrude "Выдавливание133" join sketch "Эскиз169" distance "d1112" = 1.5; taper "d1113" = 0 deg
chamfer "Фаска49" distance "d1114" = 0.6; stored, may be unused: second distance "d1115" = 2, angle "d1116" = 45 deg
fillet "Сопряжение58" dims "d1117" = 2, "d1118" = 1
feature "ᅎ耀ᅐ耀ᅒ耀ᅔ耀ᅖ耀ᅘ耀ᅚ耀ᅜ耀" dims "d0" = 504 deg (derived), "d1" = 12.56644 (derived), "d2" = 201.062 (derived), "d3" = 16 (derived), "d4" = 72 deg (derived), "d5" = 16, "d6" = 200, "d7" = 1000, "d8" = 0, "d9" = 50, "d11" = 201, "d12" = 300, "d13" = 200, "d14" = 16, "d15" = 0, "d16" = 16, "d18" = 30.5, "d19" = 30.5 (= d18), "d20" = 20, "d22" = 30.5 (= d18), "d23" = 20, "d25" = 30.5 (= d19), "d28" = 3.3, "d29" = 4.8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
feature "寄耀密耀寈耀寊耀富耀寎耀寐耀寒耀" dims "d0" = 504 deg (derived), "d1" = 12.56644 (derived), "d2" = 201.062 (derived), "d3" = 16 (derived), "d4" = 72 deg (derived), "d5" = 16, "d6" = 200, "d7" = 1000, "d8" = 0, "d9" = 50, "d11" = 201, "d12" = 300, "d13" = 200, "d14" = 16, "d15" = 0, "d16" = 16, "d18" = 30.5, "d19" = 30.5 (= d18), "d20" = 20, "d22" = 30.5 (= d18), "d23" = 20, "d25" = 30.5 (= d19), "d28" = 3.3, "d29" = 4.8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
node "Рейки"
node "Спроецированная петля2"
node "ЛДСП"
node "Эскиз — прямоугольный массив1" dims "d22" = 30.5 (= d18), "d25" = 30.5 (= d19)
node "Шкивы"
node "Спроецированная петля3"
node "Спроецированная петля4"
node "Спроецированная петля5"
node "Спроецированная петля6"
node "Спроецированная петля7"
node "Спроецированная петля8"
node "Эскиз — круговой массив1" dims "d92" = 360 deg (derived)
node "Эскиз — прямоугольный массив2" dims "d106" = 31.1 (derived), "d109" = 31.1 (derived)
node "Спроецированная петля9"
node "Спроецированная петля10"
node "Лапки"
node "Спроецированная петля11"
node "Спроецированная петля13"
node "Дека"
node "Спроецированная петля14"
node "АКБ"
node "Спроецированная петля15"
node "Шкив ведущий"
node "Спроецированная петля17"
node "Спроецированная петля18"
node "Шкив ведомый"
node "Спроецированная петля19"
node "Эскиз — прямоугольный массив3" dims "d213" = 31.1 (derived), "d216" = 31.1 (derived)
node "Крепление мотора"
node "Спроецированная петля20"
node "Спроецированная петля21"
node "Спроецированная петля23"
node "Спроецированная петля24"
node "Крепление ведомого"
node "Спроецированная петля25"
node "Спроецированная петля31"
node "Спроецированная петля32"
node "Спроецированная петля33"
node "Спроецированная петля34"
node "Эскиз — прямоугольный массив5" dims "d389" = 67.85896 (derived), "d392" = 10
node "Фанерка верх"
node "Спроецированная петля35"
node "Двигатели тест модели"
node "Каретка"
node "Спроецированная петля48"
node "Рельса"
node "Спроецированная петля49"
node "Ремень"
node "Эскиз — прямоугольный массив9" dims "d579" = 8 (derived), "d582" = 12 (derived)
node "Спроецированная петля51"
node "Спроецированная петля52"
node "Рельса 2"
node "Спроецированная петля53"
node "Спроецированная петля55"
node "Спроецированная петля56"
node "Спроецированная петля57"
node "Спроецированная петля58"
node "Каретка 2"
node "Ограничитель"
node "Серва"
node "Спроецированная петля59"
node "Эскиз — прямоугольный массив10" dims "d694" = 3.925, "d697" = 10
node "Эскиз — прямоугольный массив11" dims "d701" = 3.925, "d704" = 10
node "Рейка"
node "Шестеренка"
node "Спроецированная петля60"
node "Эскиз — прямоугольный массив12" dims "d720" = 24 (derived), "d723" = 12 (derived)
node "Спроецированная петля61"
node "Крепление ремня"
node "Спроецированная петля62"
node "Эскиз — прямоугольный массив13" dims "d764" = 2 (derived), "d767" = 10
node "Спроецированная петля63"
node "Спроецированная петля64"
node "Спроецированная петля65"
node "Спроецированная петля66"
node "Крепление маркера"
node "Твердое тело31"
node "Спроецированная петля67"
body "SRF1"
node "Спроецированная петля69"
node "Спроецированная петля70"
node "Спроецированная петля71"
node "Спроецированная петля72"
node "Спроецированная петля73"
node "Спроецированная петля74"
node "Спроецированная петля75"
node "Эскиз — прямоугольный массив14" dims "d975" = 31.1 (derived), "d978" = 31.1 (derived)
node "Спроецированная петля76"
node "Эскиз — прямоугольный массив15" dims "d998" = 31.1 (derived), "d1001" = 31.1 (derived)
node "Винт"
node "Спроецированная петля77"
node "Рукоятка"
node "Эскиз — круговой массив3" dims "d1035" = 360 deg (derived)
body "SRF2"
node "Маркер"
node "Усиление"
node "Эскиз — прямоугольный массив16" dims "d1067" = 75.73958 (derived), "d1070" = 10
node "Спроецированная петля80"
node "Спроецированная петля81"
node "Спроецированная петля82"
node "Твердое тело36"
node "Спроецированная петля83"
node "Спроецированная петля84"
node "Спроецированная петля85"
node "Спроецированная петля86"
